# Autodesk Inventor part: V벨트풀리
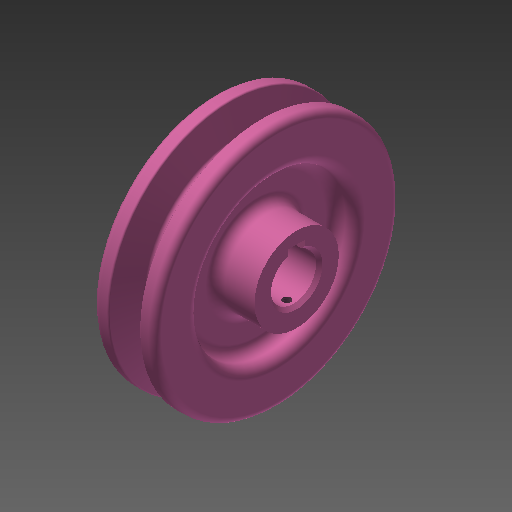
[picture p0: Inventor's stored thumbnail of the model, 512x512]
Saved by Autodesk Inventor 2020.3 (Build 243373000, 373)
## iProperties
Created: 2015-11
Part Number: V벨트풀리
Material: 강철, 탄소
Document SubType Name: Modeling
Designer: mduedu
Density: 1 g/cm^3
Appearance: 분홍색
Author: mduedu
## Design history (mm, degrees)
sketch "스케치1"
  geometry: L1 (-9.5, 0)-(9.5, 0); L2 (0, 0)-(0, 37.7); L3 (-4.825, 37.7)-(-9.5, 37.7); L4 (-9.5, 37.7)-(-9.5, 0); L5 (0, 28.7)-(-2.074, 28.7); L6 (-2.074, 28.7)-(-4.825, 37.7); L7 (4.825, 37.7)-(9.5, 37.7); L8 (9.5, 37.7)-(9.5, 0); L9 (0, 28.7)-(2.074, 28.7); L10 (2.074, 28.7)-(4.825, 37.7); L11 (-9.5, 35)-(9.5, 35); 3 further points
  constraints: 22 end point, 7 point on line, 4 perpendicular, 3 symmetric about line, 1 coincident, 1 horizontal, 1 horizontal alignment, 1 midpoint, 1 vertical
  dimensions: "d0" = 19 distance of L1.start L1.end; "d2" = 75.4 diameter of L2.end L1 (derived); "d3" = 34 deg angle of L10 L6; "d4" = 6.3 distance between parallel lines of L11 L9; "d5" = 2.7 distance between parallel lines of L7 L11; "d6" = 8 distance of point (4, 35) point (-4, 35); "d7" = 70 diameter of L11 L1
revolve "회전1" sketch "스케치1" stored, may be unused: angle "d8" = 90 deg
sketch "스케치2"
  geometry: C1 r 24 at (0, 0); C2 r 13 at (0, 0); 1 further point
  constraints: 2 centre point, 2 coincident
  dimensions: "d9" = 48 diameter of C1; "d10" = 26 diameter of C2
extrude "돌출1" cut sketch "스케치2" distance "d11" = 6; taper "d12" = 0 deg
extrude "돌출3" join sketch "스케치2" distance "d37" = 6; taper "d38" = 0 deg
fillet "모깎기1" dims "d13" = 3
fillet "모깎기2" dims "d14" = 3
fillet "모깎기3" dims "d15" = 1, "d16" = 0.5, "d17" = 2
hole "구멍1" diameter "d20" = 14; stored, may be unused: countersink angle "d24" = 90 deg, drill point angle "d26" = 118 deg; dims "d21" = 6, "d22" = 4, "d23" = 2, "d25" = 8, "d61" = 10, "d62" = 10
sketch "스케치3"
  geometry: L1 (-2.5, 0)-(2.5, 0); L2 (2.5, 0)-(2.5, 9.3); L3 (2.5, 9.3)-(-2.5, 9.3); L4 (-2.5, 9.3)-(-2.5, 0); 2 further points
  constraints: 8 end point, 2 parallel, 1 coincident, 1 horizontal, 1 midpoint, 1 perpendicular
  dimensions: "d27" = 5 distance of L2.end L3.end; "d29" = 9.3 distance of L3.end L1.start
extrude "돌출2" cut sketch "스케치3" extent not by distance; stored distance "d30" = 6; taper "d31" = 0 deg
chamfer "모따기1" distance "d32" = 1; stored, may be unused: second distance "d33" = 2, angle "d34" = 45 deg
node "작업 평면1"
sketch "스케치4"
  geometry: L1 (19, -27)-(19, 27) reference; 2 further points
  constraints: 1 horizontal alignment
  dimensions: "d52" = 22 distance from line of L1 point (-3, 0)
hole "구멍2" sketch "스케치4" at (-3, 0) diameter "d42" = 2.459; stored, may be unused: countersink angle "d46" = 90 deg, drill point angle "d48" = 118 deg; dims "d43" = 6, "d44" = 4, "d45" = 2, "d47" = 8
chamfer "모따기3" distance "d58" = 1; stored, may be unused: second distance "d59" = 2, angle "d60" = 45 deg
node "솔리드1"
mirror "대칭1"
